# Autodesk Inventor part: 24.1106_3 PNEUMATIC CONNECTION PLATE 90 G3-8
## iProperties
Created: 2007-01
Part Number: 24.1106_3 PNEUMATIC CONNECTION PLATE 90 G3-8
Document SubType Name: Modeling
Designer: Andy Moles
Material: Aluminum-6061
Mass: 302.963 g
Surface Area: 230.685 cm^2
Volume: 111.794 cm^3
Density: 2.71 g/cm^3
Author: Andy Moles
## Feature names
1. Extrusion1
2. Hole1
3. Hole2
4. Fillet1
5. Hole3
6. Hole4
7. Extrusion2
8. Chamfer1
